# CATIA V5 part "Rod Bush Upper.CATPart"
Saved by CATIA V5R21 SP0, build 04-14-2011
Part number: Rod Bush Upper
Bounding box of the stored display mesh (mm): x -12 to 12, y -11.818 to 11.818, z -21 to 21
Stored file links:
  D:\CATIA V5R21 E-RESOURCES\CATIA-V5R21\catia-v5r21-Prts\c13_catia_v5r21_prt\c13_catia_v5r21_figr_13-41\Part & Asm files\Rod Bush Upper.CATPart
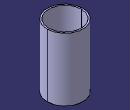
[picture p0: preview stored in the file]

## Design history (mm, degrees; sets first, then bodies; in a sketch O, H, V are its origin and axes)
Body1 (main body)
  Sketch1 on xy-plane, origin (0, 0, 0), H (1, 0, 0), V (0, 1, 0)
    circle A1 centre (0, 0) radius 11
    circle A2 centre (0, 0) radius 12
    point P1 (0, 0)
    radius A2 = 12
    radius A1 = 11
    coincidence: P1 H
    concentricity: A1 A2
  Pad1: profile Sketch1, direction (0, 0, 1), length 21, mirrored extent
